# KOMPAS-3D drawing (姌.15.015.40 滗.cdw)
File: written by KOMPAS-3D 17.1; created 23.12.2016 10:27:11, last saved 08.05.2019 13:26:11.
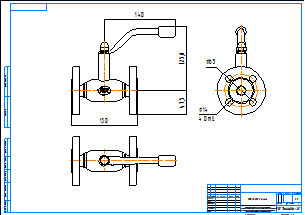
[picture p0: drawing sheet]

Sheet 1: A2, landscape

Title block, sheet 1: name: КШ.15.015.40 фф; material: Внимание! Данный продукт является объектом авторского права ООО «Торговый Дом АДЛ». / Запрещается изменение, копирование, распространение / (в том числе путем копирования на другие сайты и ресурсы в Интернете) / или любое иное использование информации и объектов без предварительного / согласия правообладателя (ООО «Торговый Дом АДЛ»).; sheets: 1; organisation: ООО "Торговый дом АДЛ"; sheet format: A2; stored path: C:\Users\tra\Desktop\2д чертежи\Шаровые краны БИВАЛ\КШ_Бивал_серия_14_15\KOMPAS_2D\КШ.15.015.40 фф.cdw

Views: Спереди 4, Проекционный вид 5, Проекционный вид 6
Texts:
  Klimkovich
  ADL
Dimensions and other numbers on the sheet: 130; 140; 125,8; 47,5; 65; 14; 4 Отв.; 1:1; 1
